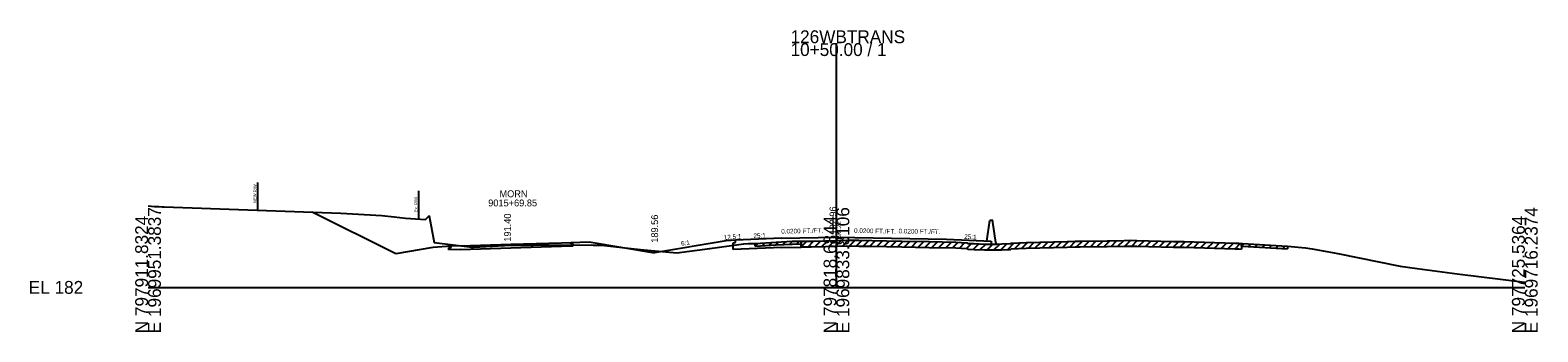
# Model space of a CAD drawing. Extents: x -6494 to 1970605, y -10 to 798140.
# Drawn here: x -25.7 to 302.8, y 2990.3 to 3056.1 of the extents above; entities that cross this region are included whole.
import ezdxf

# ---------------------------------------------------------------- set-up
doc = ezdxf.new("R2010")
doc.units = 0
for name, color, linetype in [('RD_GPK_XS_Cell', 7, 'Continuous'), ('RD_XS_Base', 7, 'Continuous'), ('RD_XS_EarthShd', 7, 'Continuous'), ('RD_XS_ExGround', 7, 'Continuous'), ('RD_XS_ExPaveRet', 7, 'Continuous'), ('RD_XS_ExRW', 7, 'Continuous'), ('RD_XS_MedBWall', 7, 'Continuous'), ('RD_XS_Misc_Line', 7, 'Continuous'), ('RD_XS_NewRW', 7, 'Continuous'), ('RD_XS_Pave', 7, 'Continuous'), ('RD_XS_PaveOvlay', 7, 'Continuous'), ('RD_XS_PaveShd', 7, 'Continuous'), ('RD_XS_TieSlope', 7, 'Continuous'), ('RD_XS_TX_Elev_EX', 7, 'Continuous'), ('RD_XS_TX_Elev_PR', 7, 'Continuous'), ('RD_XS_TX_Misc', 7, 'Continuous'), ('RD_XS_TX_Profile', 7, 'Continuous'), ('RD_XS_TX_ShdSlope', 7, 'Continuous'), ('RD_XS_TX_Slope', 7, 'Continuous'), ('RD_XS_TX_Station', 7, 'Continuous')]:
    doc.layers.add(name, color=color, linetype=linetype)

msp = doc.modelspace()

# ---------------------------------------------------------------- linework, layer by layer
at = {"layer": 'RD_GPK_XS_Cell'}
for p, q in [((150, 3000), (150, 3053.23)), ((0, 3000), (150, 3000)), ((150, 3000), (300, 3000))]:
    msp.add_line(p, q, dxfattribs=at)
at = {"layer": 'RD_XS_Base'}
for p, q in [((92.12, 3009.51), (92.12, 3009.81)), ((92.62, 3009.52), (92.12, 3009.51)), ((92.62, 3009.04), (92.62, 3009.52)), ((127.5, 3009.74), (128, 3009.76)), ((127.5, 3008.26), (127.5, 3009.74)), ((128, 3009.76), (128, 3010.32)), ((65.53, 3008.67), (66.03, 3008.69)), ((65.53, 3008.19), (65.53, 3008.67)), ((68.04, 3008.27), (65.53, 3008.19)), ((66.03, 3008.69), (66.03, 3008.99)), ((90.11, 3008.96), (92.62, 3009.04)), ((138, 3008.68), (127.5, 3008.26)), ((138, 3008.68), (142.31, 3008.77))]:
    msp.add_line(p, q, dxfattribs=at)
at = {"layer": 'RD_XS_EarthShd'}
for p, q in [((92.12, 3009.81), (96.13, 3009.93)), ((128, 3010.32), (126, 3010.16)), ((66.03, 3008.99), (62.02, 3008.67))]:
    msp.add_line(p, q, dxfattribs=at)
at = {"layer": 'RD_XS_ExGround'}
msp.add_lwpolyline([(0, 3017.74), (1.41, 3017.66), (1.84, 3017.63), (2.37, 3017.6), (3.1, 3017.55), (3.53, 3017.55), (42.03, 3016.19), (50.94, 3015.65), (53.65, 3015.41), (56.12, 3015.09), (60.42, 3014.8), (60.74, 3015.1), (61.25, 3015.6), (62.36, 3009.78), (70.04, 3008.82), (70.47, 3008.75), (70.95, 3008.78), (77.65, 3009.16), (83.94, 3009.22), (88.97, 3009.28), (96.99, 3009.22), (98.46, 3009.2), (99.49, 3009.1), (105.9, 3008.38), (108.02, 3008.18), (115.2, 3007.53), (122.4, 3008.5), (126.66, 3009.06), (129.85, 3009.5), (130.81, 3009.54), (132.3, 3009.6), (136.88, 3009.87), (140.32, 3010.06), (144.46, 3010.11), (147.62, 3010.17), (150, 3010.22), (152.27, 3010.3), (154.85, 3010.26), (157.68, 3010.21), (160.91, 3010.15), (164.27, 3010.1), (170.21, 3009.97), (176.02, 3009.86), (177.18, 3009.79), (178.38, 3009.74), (178.61, 3009.6), (180.01, 3009.54), (182.27, 3009.44), (184.02, 3009.44), (184.94, 3009.43), (186.02, 3009.46), (187.92, 3009.54), (188.11, 3009.65), (191.32, 3009.79), (200.26, 3010.03), (202.03, 3010.08), (203.11, 3010.09), (208.99, 3010.17), (212.69, 3010.24), (214.13, 3010.26), (215.44, 3010.22), (217.99, 3010.15), (223.42, 3010.03), (225.8, 3009.99), (236.79, 3009.67), (237.66, 3009.65), (238.5, 3009.59), (248.26, 3009.02), (252.23, 3008.59), (253.68, 3008.42), (259.23, 3007.38), (272.83, 3004.6), (276.57, 3004.09), (285.24, 3002.96), (300, 3001.16)], dxfattribs=at)
at = {"layer": 'RD_XS_ExPaveRet'}
for p, q in [((132.3, 3008.98), (132.3, 3009.6)), ((136.88, 3009.25), (140.32, 3009.43)), ((140.32, 3009.43), (142.31, 3009.46)), ((142.31, 3008.83), (142.31, 3010.08)), ((142.31, 3010.08), (142.31, 3009.46)), ((238.26, 3009.61), (238.26, 3008.36)), ((238.26, 3008.98), (238.26, 3009.61)), ((132.3, 3008.98), (136.88, 3009.25)), ((142.31, 3008.83), (144.46, 3008.86)), ((144.46, 3008.86), (147.62, 3008.92)), ((147.62, 3008.92), (150, 3008.97)), ((150, 3008.97), (152.27, 3009.05)), ((152.27, 3009.05), (154.85, 3009.01)), ((154.85, 3009.01), (157.68, 3008.96)), ((157.68, 3008.96), (160.91, 3008.9)), ((160.91, 3008.9), (164.27, 3008.85)), ((164.27, 3008.85), (170.21, 3008.72)), ((170.21, 3008.72), (176.02, 3008.61)), ((176.02, 3008.61), (177.18, 3008.54)), ((177.18, 3008.54), (178.38, 3008.49)), ((178.38, 3008.49), (178.61, 3008.35)), ((178.61, 3008.35), (180.01, 3008.29)), ((180.01, 3008.29), (182.27, 3008.19)), ((182.27, 3008.19), (184.02, 3008.19)), ((184.02, 3008.19), (184.94, 3008.18)), ((184.94, 3008.18), (186.02, 3008.21)), ((186.02, 3008.21), (187.92, 3008.29)), ((187.92, 3008.29), (188.11, 3008.4)), ((188.11, 3008.4), (191.32, 3008.54)), ((191.32, 3008.54), (200.26, 3008.78)), ((200.26, 3008.78), (202.03, 3008.83)), ((202.03, 3008.83), (203.11, 3008.84)), ((203.11, 3008.84), (208.99, 3008.92)), ((208.99, 3008.92), (212.69, 3008.99)), ((212.69, 3008.99), (214.13, 3009.01)), ((214.13, 3009.01), (215.44, 3008.97)), ((215.44, 3008.97), (217.99, 3008.9)), ((217.99, 3008.9), (223.42, 3008.78)), ((223.42, 3008.78), (225.8, 3008.74)), ((225.8, 3008.74), (236.79, 3008.42)), ((236.79, 3008.42), (237.66, 3008.4)), ((237.66, 3008.4), (238.26, 3008.36)), ((238.26, 3008.98), (238.5, 3008.97)), ((238.5, 3008.97), (248.26, 3008.39)), ((248.26, 3009.02), (248.26, 3008.39))]:
    msp.add_line(p, q, dxfattribs=at)
at = {"layer": 'RD_XS_ExRW'}
msp.add_line((58.95, 3021.03), (58.95, 3015.03), dxfattribs=at)
at = {"layer": 'RD_XS_MedBWall'}
for p, q in [((182.74, 3010.11), (183.41, 3014.59)), ((184.07, 3014.59), (183.41, 3014.59)), ((184.07, 3014.23), (184.07, 3014.59)), ((184.74, 3009.75), (184.07, 3014.23)), ((184.74, 3009.75), (184.74, 3009.43))]:
    msp.add_line(p, q, dxfattribs=at)
at = {"layer": 'RD_XS_Misc_Line'}
for p, q in [((132.3, 3008.98), (132.97, 3009.64)), ((133.8, 3009.07), (134.47, 3009.73)), ((135.3, 3009.16), (135.97, 3009.82)), ((136.8, 3009.24), (137.47, 3009.9)), ((138.3, 3009.33), (138.97, 3009.99)), ((139.81, 3009.41), (140.46, 3010.06)), ((141.31, 3009.45), (141.94, 3010.08)), ((142.31, 3008.83), (143.57, 3010.1)), ((143.81, 3008.85), (145.08, 3010.12)), ((145.31, 3008.87), (146.58, 3010.15)), ((146.81, 3008.9), (148.09, 3010.18)), ((148.31, 3008.93), (149.59, 3010.21)), ((149.81, 3008.97), (151.1, 3010.26)), ((151.31, 3009.02), (152.59, 3010.29)), ((152.81, 3009.04), (154.05, 3010.27)), ((154.31, 3009.02), (155.54, 3010.25)), ((155.81, 3008.99), (157.04, 3010.22)), ((157.31, 3008.97), (158.54, 3010.19)), ((158.81, 3008.94), (160.04, 3010.17)), ((160.32, 3008.91), (161.54, 3010.14)), ((161.82, 3008.88), (163.05, 3010.11)), ((163.32, 3008.86), (164.55, 3010.09)), ((164.82, 3008.83), (166.04, 3010.06)), ((166.32, 3008.8), (167.54, 3010.03)), ((167.82, 3008.77), (169.04, 3010)), ((169.32, 3008.74), (170.55, 3009.97)), ((170.82, 3008.71), (172.05, 3009.94)), ((172.32, 3008.68), (173.55, 3009.91)), ((173.82, 3008.65), (175.05, 3009.88)), ((175.32, 3008.63), (176.53, 3009.83)), ((176.82, 3008.56), (178.01, 3009.75)), ((178.32, 3008.49), (179.41, 3009.57)), ((179.83, 3008.3), (181.02, 3009.5)), ((181.33, 3008.23), (182.53, 3009.44)), ((182.83, 3008.19), (184.08, 3009.44)), ((184.33, 3008.19), (185.59, 3009.45)), ((185.83, 3008.21), (187.13, 3009.51)), ((187.33, 3008.26), (188.74, 3009.68)), ((188.83, 3008.43), (190.14, 3009.74)), ((190.33, 3008.49), (191.63, 3009.79)), ((191.83, 3008.55), (193.12, 3009.84)), ((193.33, 3008.59), (194.62, 3009.88)), ((194.83, 3008.63), (196.12, 3009.92)), ((196.33, 3008.67), (197.62, 3009.96)), ((197.83, 3008.72), (199.12, 3010)), ((199.34, 3008.76), (200.62, 3010.04)), ((200.84, 3008.8), (202.12, 3010.08)), ((202.34, 3008.84), (203.6, 3010.1)), ((203.84, 3008.85), (205.11, 3010.12)), ((205.34, 3008.87), (206.61, 3010.14)), ((206.84, 3008.9), (208.11, 3010.16)), ((208.34, 3008.92), (209.61, 3010.18)), ((209.84, 3008.94), (211.11, 3010.21)), ((211.34, 3008.96), (212.61, 3010.24)), ((212.84, 3008.99), (214.12, 3010.26)), ((214.34, 3009.01), (215.55, 3010.22)), ((215.84, 3008.96), (217.06, 3010.17)), ((217.34, 3008.92), (218.56, 3010.14)), ((218.85, 3008.88), (220.07, 3010.1)), ((220.35, 3008.85), (221.57, 3010.07)), ((221.85, 3008.82), (223.07, 3010.04)), ((223.35, 3008.78), (224.58, 3010.01)), ((224.85, 3008.76), (226.08, 3009.99)), ((226.35, 3008.73), (227.56, 3009.94)), ((227.85, 3008.68), (229.06, 3009.9)), ((229.35, 3008.64), (230.57, 3009.85)), ((230.85, 3008.6), (232.07, 3009.81)), ((232.35, 3008.55), (233.57, 3009.77)), ((233.85, 3008.51), (235.07, 3009.72)), ((235.35, 3008.47), (236.57, 3009.68)), ((236.85, 3008.42), (238.06, 3009.62)), ((238.26, 3008.98), (238.85, 3009.57)), ((239.76, 3008.89), (240.35, 3009.48)), ((241.26, 3008.81), (241.85, 3009.4)), ((242.77, 3008.72), (243.36, 3009.31)), ((244.27, 3008.63), (244.86, 3009.22)), ((245.77, 3008.54), (246.36, 3009.13)), ((247.27, 3008.45), (247.86, 3009.04))]:
    msp.add_line(p, q, dxfattribs=at)
at = {"layer": 'RD_XS_NewRW'}
msp.add_line((23.88, 3022.83), (23.88, 3016.83), dxfattribs=at)
at = {"layer": 'RD_XS_Pave'}
for p, q in [((68.04, 3009.05), (79.08, 3009.4)), ((79.08, 3009.4), (90.11, 3009.74)), ((138, 3010.72), (150, 3010.96)), ((150, 3010.96), (174, 3010.48)), ((68.04, 3008.27), (79.08, 3008.62)), ((79.08, 3008.62), (90.11, 3008.96))]:
    msp.add_line(p, q, dxfattribs=at)
at = {"layer": 'RD_XS_PaveOvlay'}
for p, q in [((142.31, 3010.08), (144.46, 3010.11)), ((142.31, 3010.08), (142.31, 3008.77)), ((144.46, 3010.11), (147.62, 3010.17)), ((147.62, 3010.17), (150, 3010.22)), ((150, 3010.22), (152.27, 3010.3)), ((152.27, 3010.3), (154.85, 3010.26)), ((154.85, 3010.26), (157.68, 3010.21)), ((157.68, 3010.21), (160.91, 3010.15)), ((160.91, 3010.15), (164.27, 3010.1)), ((164.27, 3010.1), (170.21, 3009.97)), ((170.21, 3009.97), (176.02, 3009.86)), ((176.02, 3009.86), (177.18, 3009.79)), ((177.18, 3009.79), (178.38, 3009.74)), ((178.38, 3009.74), (178.61, 3009.6)), ((178.61, 3009.6), (180.01, 3009.54)), ((180.01, 3009.54), (182.27, 3009.44)), ((182.27, 3009.44), (183.74, 3009.44))]:
    msp.add_line(p, q, dxfattribs=at)
at = {"layer": 'RD_XS_PaveShd'}
for p, q in [((90.11, 3009.74), (92.12, 3009.81)), ((138, 3010.72), (128, 3010.32)), ((174, 3010.48), (183.74, 3010.09)), ((183.74, 3010.09), (183.74, 3009.44)), ((68.04, 3009.05), (66.03, 3008.99))]:
    msp.add_line(p, q, dxfattribs=at)
at = {"layer": 'RD_XS_TieSlope'}
for p, q in [((53.99, 3007.33), (35.78, 3016.41)), ((96.13, 3009.93), (110.39, 3007.56)), ((126, 3010.16), (110.39, 3007.56)), ((62.02, 3008.67), (53.99, 3007.33)), ((110.39, 3007.56), (110.39, 3007.97))]:
    msp.add_line(p, q, dxfattribs=at)

# ---------------------------------------------------------------- texts
at = {"layer": 'RD_GPK_XS_Cell'}
for s, p in [('126WBTRANS', (140, 3053.23)), ('10+50.00 / 1', (140, 3050.43)), ('EL 182', (-26, 2998.6))]:
    msp.add_text(s, height=2.8, dxfattribs=at).set_placement(p)
for s, p in [('E 1969951.3837', (2.8, 2990)), ('E 1969833.8106', (152.8, 2990)), ('E 1969716.2374', (302.8, 2990)), ('N 797911.8324', (0, 2990)), ('N 797818.6844', (150, 2990)), ('N 797725.5364', (300, 2990))]:
    msp.add_text(s, height=2.8, rotation=90, dxfattribs=at).set_placement(p)
at = {"layer": 'RD_XS_ExRW'}
msp.add_text('Ex. R/W ', height=0.65, rotation=90, dxfattribs=at).set_placement((58.7, 3016.41))
at = {"layer": 'RD_XS_NewRW'}
msp.add_text('NEW R/W ', height=0.65, rotation=90, dxfattribs=at).set_placement((23.62, 3018.39))
at = {"layer": 'RD_XS_TX_Elev_EX'}
msp.add_text('192.22', height=1, rotation=90, dxfattribs=at).set_placement((151, 3010.22))
at = {"layer": 'RD_XS_TX_Elev_PR'}
for s, p in [(' 191.40', (79.08, 3009.4)), (' 192.96', (150, 3010.96))]:
    msp.add_text(s, height=1.5, rotation=90, dxfattribs=at).set_placement(p)
at = {"layer": 'RD_XS_TX_Misc'}
msp.add_text('189.56', height=1.5, rotation=90, dxfattribs=at).set_placement((111.14, 3009.72))
at = {"layer": 'RD_XS_TX_Profile'}
for rotation, p in [(2.2906, (131.94, 3010.73)), (357.7094, (177.83, 3010.58))]:
    msp.add_text('25:1', height=1, rotation=rotation, dxfattribs=at).set_placement(p)
at = {"layer": 'RD_XS_TX_ShdSlope'}
msp.add_text('12.5:1', height=1, rotation=4.5739, dxfattribs=at).set_placement((125.5, 3010.37))
at = {"layer": 'RD_XS_TX_Slope'}
for s, rotation, p in [('0.0200 FT./FT.', 1.1458, (137.98, 3011.72)), ('0.0200 FT./FT.', 358.8542, (153.83, 3011.89)), ('0.0200 FT./FT.', 358.8542, (163.53, 3011.78)), ('6:1', 9.4623, (116.22, 3009.04))]:
    msp.add_text(s, height=1, rotation=rotation, dxfattribs=at).set_placement(p)
at = {"layer": 'RD_XS_TX_Station'}
for s, p in [('MORN', (76.57, 3019.65)), ('9015+69.85', (74.12, 3017.65))]:
    msp.add_text(s, height=1.5, dxfattribs=at).set_placement(p)

doc.saveas('drawing.dxf')
